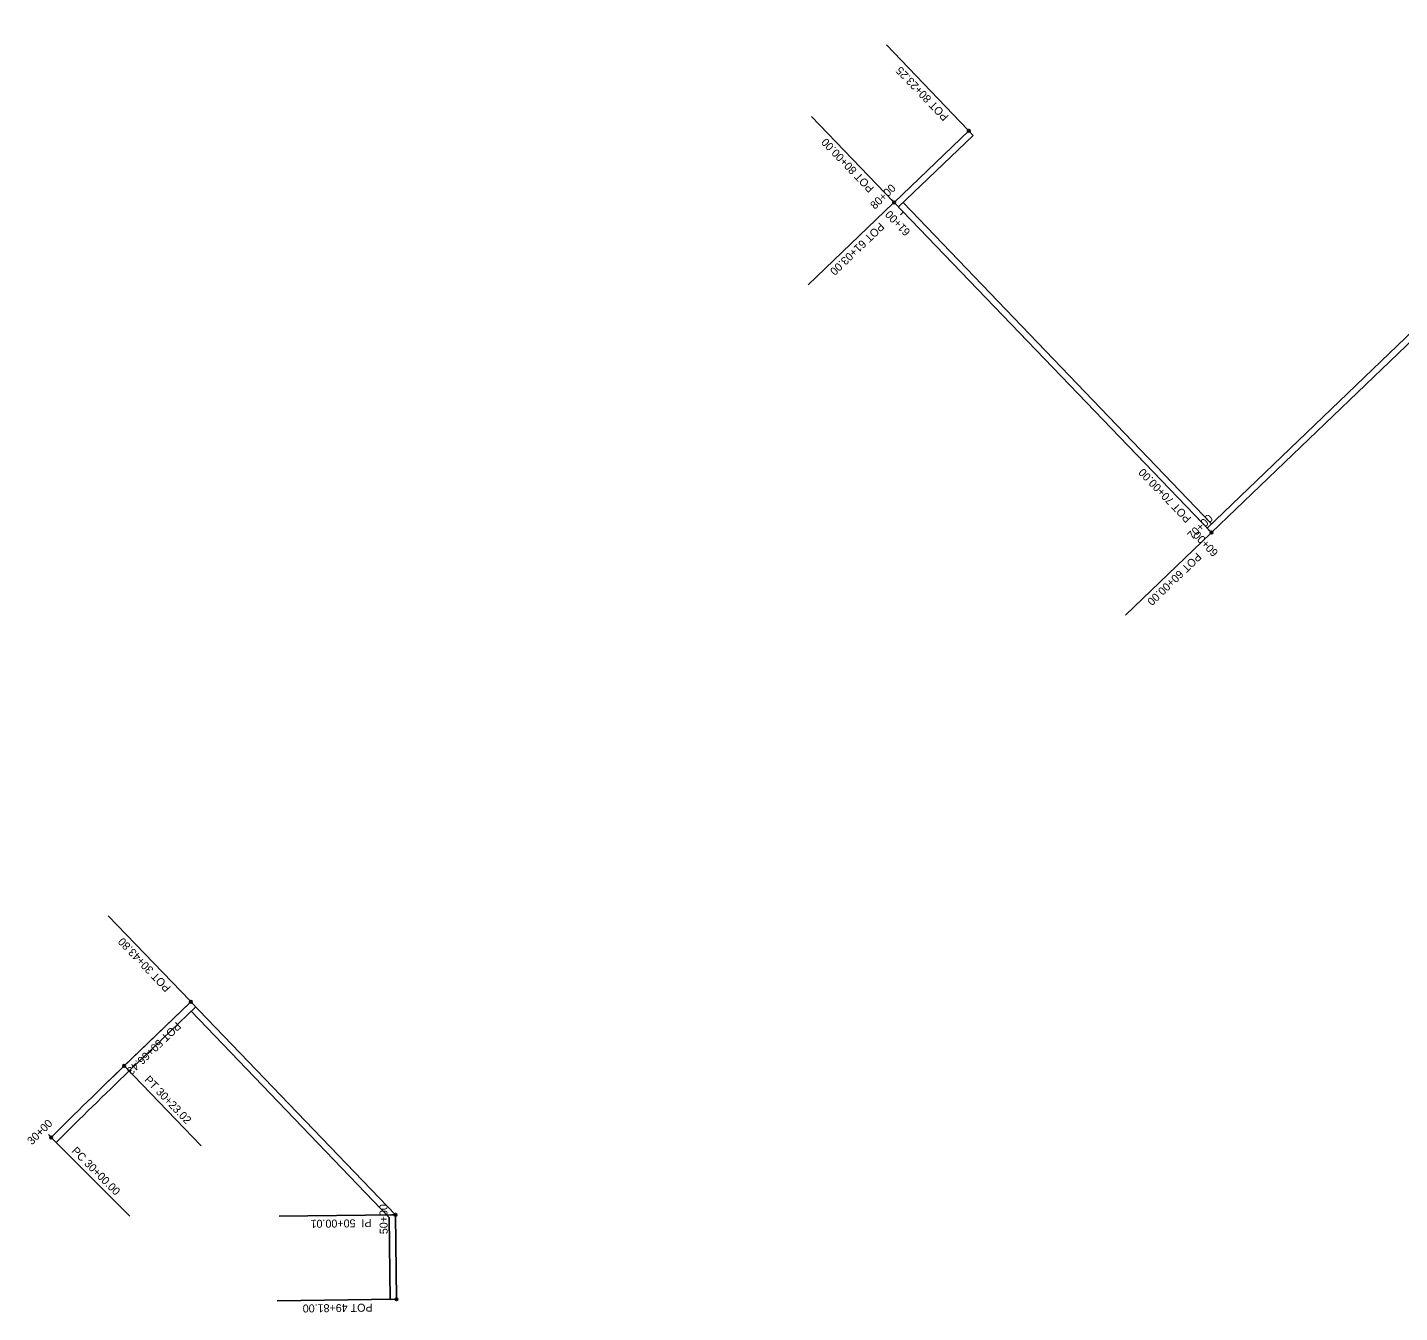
# Model space of a CAD drawing. Extents: x 2255019 to 2255637, y 13790912 to 13791457.
# Drawn here: x 2255019.4 to 2255328, y 13790912.1 to 13791201.2 of the extents above; entities that cross this region are included whole.
import ezdxf

# ---------------------------------------------------------------- set-up
doc = ezdxf.new("R2010")
doc.units = 0
doc.layers.add('D_ALIGN_ANNO_1', color=7, linetype='Continuous')
doc.layers.add('Struc_Wall', color=7, linetype='Continuous')

msp = doc.modelspace()

# ---------------------------------------------------------------- linework, layer by layer
at = {"layer": 'D_ALIGN_ANNO_1'}
for p, q in [((2255230.94, 13791178.16), (2255212.61, 13791197.25)), ((2255214.17, 13791162.06), (2255195.8, 13791181.19)), ((2255214.16, 13791161.63), (2255195.03, 13791143.26)), ((2255214.38, 13791161.84), (2255213.75, 13791162.49)), ((2255216.46, 13791159.68), (2255215.81, 13791159.05)), ((2255285.51, 13791087.77), (2255267.14, 13791106.9)), ((2255285.5, 13791087.34), (2255266.37, 13791068.97)), ((2255285.72, 13791087.55), (2255285.07, 13791086.93)), ((2255285.72, 13791087.55), (2255285.1, 13791088.2)), ((2255056, 13790982.2), (2255037.62, 13791001.33)), ((2255055.99, 13790981.77), (2255036.9, 13790963.44)), ((2255055.99, 13790981.77), (2255036.9, 13790963.44)), ((2255041.42, 13790967.37), (2255058.52, 13790949.57)), ((2255024.77, 13790951.47), (2255024.14, 13790952.11)), ((2255024.98, 13790951.26), (2255042.48, 13790933.77)), ((2255101.91, 13790934.07), (2255076.02, 13790933.75)), ((2255102.21, 13790934.07), (2255101.31, 13790934.06)), ((2255102.21, 13790934.07), (2255101.31, 13790934.06)), ((2255102.21, 13790934.07), (2255101.31, 13790934.06)), ((2255102.15, 13790915.07), (2255075.63, 13790914.74)), ((2255102.15, 13790915.07), (2255075.63, 13790914.74)), ((2255102.15, 13790915.07), (2255075.63, 13790914.74))]:
    msp.add_line(p, q, dxfattribs=at)
for centre in [(2255231.15, 13791177.95), (2255214.38, 13791161.84), (2255214.38, 13791161.84), (2255285.72, 13791087.55), (2255285.72, 13791087.55), (2255056.2, 13790981.98), (2255056.2, 13790981.98), (2255056.2, 13790981.98), (2255056.2, 13790981.98), (2255056.2, 13790981.98), (2255041.21, 13790967.59), (2255024.77, 13790951.47), (2255024.77, 13790951.47), (2255102.21, 13790934.08), (2255102.21, 13790934.08), (2255102.21, 13790934.08), (2255102.45, 13790915.07), (2255102.45, 13790915.07), (2255102.45, 13790915.07)]:
    msp.add_circle(centre, 0.3, dxfattribs=at)
at = {"layer": 'Struc_Wall'}
for p, q in [((2255284.74, 13791088.57), (2255402.01, 13791201.19)), ((2255285.72, 13791087.55), (2255402.99, 13791200.17)), ((2255214.38, 13791161.84), (2255231.15, 13791177.95)), ((2255215.36, 13791160.82), (2255232.13, 13791176.92)), ((2255231.15, 13791177.95), (2255232.13, 13791176.92)), ((2255285.72, 13791087.55), (2255214.38, 13791161.84)), ((2255285.76, 13791089.55), (2255216.38, 13791161.8)), ((2255041.21, 13790967.59), (2255056.2, 13790981.98)), ((2255042.31, 13790966.45), (2255057.3, 13790980.84)), ((2255102.21, 13790934.08), (2255056.2, 13790981.98)), ((2255100.8, 13790933.5), (2255056.28, 13790979.86)), ((2255025.89, 13790950.35), (2255024.77, 13790951.47)), ((2255101.03, 13790915.05), (2255100.8, 13790933.5)), ((2255102.45, 13790915.07), (2255102.21, 13790934.08)), ((2255101.03, 13790915.05), (2255102.45, 13790915.07))]:
    msp.add_line(p, q, dxfattribs=at)
for radius in [1131.33, 1129.75]:
    msp.add_arc((2255824.84, 13790151.59), radius, 133.84074, 135.0067, dxfattribs=at)

# ---------------------------------------------------------------- texts
at = {"layer": 'D_ALIGN_ANNO_1'}
for s, rotation, p in [('POT 80+23.25', 133.8407, (2255226.76, 13791181.22)), ('POT 80+00.00', 133.8407, (2255209.99, 13791165.11)), ('80+00', 43.8407, (2255210.02, 13791160.15)), ('61+00', 133.8407, (2255218.15, 13791155.32)), ('POT 61+03.00', 223.8407, (2255211.11, 13791157.45)), ('POT 70+00.00', 133.8407, (2255281.33, 13791090.82)), ('70+00', 43.8407, (2255281.36, 13791085.86)), ('60+00', 133.8407, (2255287.41, 13791083.19)), ('POT 60+00.00', 223.8407, (2255282.45, 13791083.16)), ('POT 30+43.80', 133.8407, (2255051.81, 13790985.25)), ('POT 50+66.43', 223.843, (2255052.93, 13790977.59)), ('POT 50+66.43', 223.843, (2255052.93, 13790977.59)), ('PT 30+23.02', 313.8407, (2255045.6, 13790964.32)), ('30+00', 45.0067, (2255020.45, 13790949.69)), ('PC 30+00.00', 315.0067, (2255029.23, 13790948.29)), ('50+00', 90.7179, (2255100.47, 13790929.73)), ('50+00', 90.7179, (2255100.47, 13790929.73)), ('50+00', 90.7179, (2255100.47, 13790929.73)), ('PI  50+00.01', 180.7179, (2255096.82, 13790933.11)), ('POT 49+81.00', 180.7179, (2255097.06, 13790914.1)), ('POT 49+81.00', 180.7179, (2255097.06, 13790914.1)), ('POT 49+81.00', 180.7179, (2255097.06, 13790914.1))]:
    msp.add_text(s, height=1.8, rotation=rotation, dxfattribs=at).set_placement(p)

doc.saveas('drawing.dxf')
